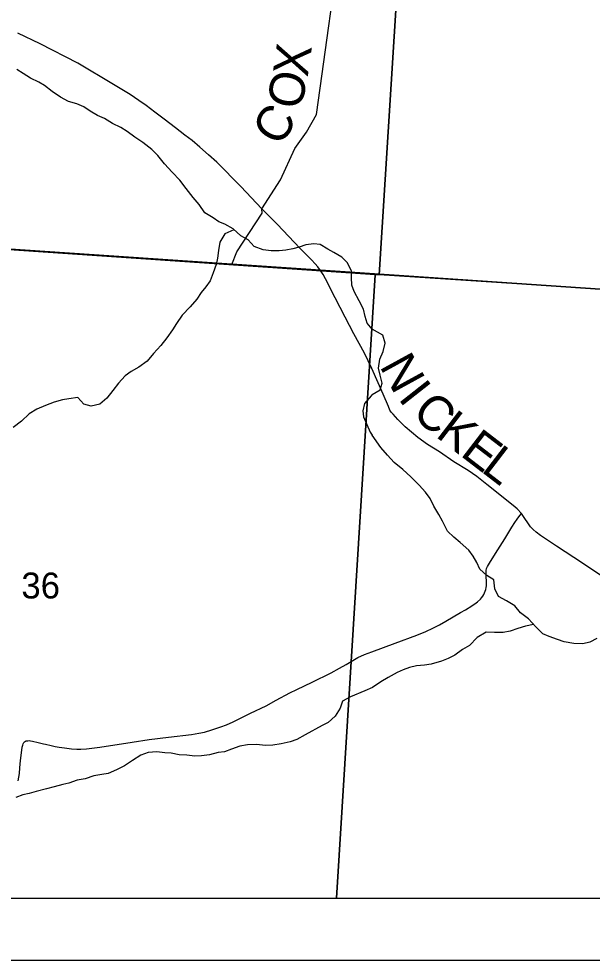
# Model space of a CAD drawing. Extents: x 39.8 to 73.8, y 13 to 35.
# Drawn here: x 43.656 to 44.581, y 26.965 to 28.484 of the extents above; entities that cross this region are included whole.
import ezdxf

# ---------------------------------------------------------------- set-up
doc = ezdxf.new("R2010")
doc.units = 0
for name, color, linetype in [('GM_X_Corporation', 7, 'Continuous'), ('GM_X_County_Road', 7, 'Continuous'), ('GM_X_County_Road_Text', 7, 'Continuous'), ('GM_X_Minor_River', 7, 'Continuous'), ('GM_X_Section_Text', 7, 'Continuous'), ('GM_X_Township_Road', 7, 'Continuous'), ('GM_X_Township_Road_Text', 7, 'Continuous'), ('SH_Data', 7, 'Continuous')]:
    doc.layers.add(name, color=color, linetype=linetype)

msp = doc.modelspace()

# ---------------------------------------------------------------- linework, layer by layer
at = {"layer": 'GM_X_Corporation'}
msp.add_lwpolyline([(43.3304, 29.7365), (43.2726, 28.9503), (43.2721, 28.9438), (43.2131, 28.1416), (43.9992, 28.0883), (44.127, 28.0796), (44.1422, 28.0786), (45.3064, 27.9996), (46.1767, 27.9406), (46.6011, 27.9118), (46.7316, 27.9029), (46.7775, 27.8998), (46.7905, 27.899), (47.095, 27.8783), (47.5149, 27.8498)], dxfattribs=at)
for points in [[(43.2893, 29.1598), (44.3, 29.0715), (44.237, 28.0712), (44.2308, 28.0712), (43.2226, 28.1399)], [(44.3, 29.0715), (45.2916, 29.0179), (45.2324, 28.0059), (44.237, 28.0712)], [(43.1433, 27.065), (48.663, 27.065), (48.663, 27.7809), (47.5414, 27.8484), (47.5149, 27.8498), (47.095, 27.8783), (46.7905, 27.899), (46.7775, 27.8998), (46.7316, 27.9029), (46.6011, 27.9118), (46.1767, 27.9406), (45.3064, 27.9996), (44.1422, 28.0786), (44.127, 28.0796), (43.9992, 28.0883), (43.2131, 28.1416)], [(43.6037, 27.065), (44.1682, 27.065), (44.2308, 28.0712), (43.2226, 28.1399), (43.1518, 27.0988)], [(44.1682, 27.065), (45.172, 27.065), (45.2324, 28.0059), (44.237, 28.0712), (44.2308, 28.0712)]]:
    msp.add_lwpolyline(points, close=True, dxfattribs=at)
at = {"layer": 'GM_X_County_Road'}
for points in [[(44.048, 28.1774), (44.0138, 28.2136), (43.9753, 28.2528), (43.9619, 28.2648), (43.9479, 28.277), (43.9353, 28.2876), (43.9238, 28.2966), (43.9085, 28.3081), (43.8902, 28.3223), (43.875, 28.3338), (43.8612, 28.3442), (43.8491, 28.3525), (43.8355, 28.3619), (43.822, 28.3701), (43.8084, 28.3782), (43.751, 28.4128), (43.6901, 28.4436), (43.6544, 28.461)], [(44.1424, 28.0781), (44.138, 28.0838), (44.1341, 28.0886), (44.1278, 28.0951), (44.1189, 28.1043), (44.109, 28.1142), (44.0729, 28.1521), (44.048, 28.1774)], [(44.4667, 27.6856), (44.4599, 27.6935), (44.4534, 27.6987), (44.411, 27.7325), (44.3944, 27.7454), (44.3807, 27.7552), (44.3578, 27.7693), (44.3343, 27.7852), (44.3153, 27.797), (44.2994, 27.8085), (44.289, 27.817), (44.2792, 27.8257), (44.2674, 27.8375), (44.2595, 27.8462), (44.2567, 27.8495), (44.2544, 27.8528), (44.2522, 27.8587), (44.2438, 27.8786), (44.2253, 27.9201), (44.2135, 27.9444), (44.1962, 27.9759), (44.182, 28.0026), (44.1659, 28.0337), (44.1505, 28.0647), (44.1467, 28.0713), (44.1424, 28.0781)], [(43.6549, 27.2544), (43.6567, 27.2663), (43.6575, 27.2752), (43.6585, 27.2873), (43.66, 27.2995), (43.6614, 27.3087), (43.662, 27.3118), (43.6628, 27.3141), (43.664, 27.3161), (43.6651, 27.3173), (43.6663, 27.3182), (43.6675, 27.3187), (43.6691, 27.3191), (43.6703, 27.3192), (43.6722, 27.3194), (43.6746, 27.3192), (43.6777, 27.3186), (43.6868, 27.3164), (43.6958, 27.3143), (43.699, 27.3134), (43.708, 27.3113), (43.7144, 27.3099), (43.7209, 27.3088), (43.7296, 27.3077), (43.741, 27.3062), (43.7496, 27.3054), (43.7557, 27.3054), (43.7649, 27.306), (43.7864, 27.309), (43.8386, 27.317), (43.8662, 27.3212), (43.8971, 27.3251), (43.9341, 27.3291), (43.9463, 27.3311), (43.9553, 27.3331), (43.9672, 27.3365), (43.9819, 27.3414), (43.9906, 27.3447), (44.0018, 27.3497), (44.0296, 27.3635), (44.0547, 27.3756), (44.071, 27.3844), (44.0929, 27.3964), (44.104, 27.402), (44.1289, 27.4137), (44.1594, 27.4289), (44.1731, 27.4362), (44.1838, 27.4424), (44.1971, 27.4504), (44.2026, 27.4533), (44.2137, 27.4582), (44.2251, 27.4627), (44.263, 27.4767), (44.2979, 27.4897), (44.3122, 27.4956), (44.3235, 27.5008), (44.3344, 27.5063), (44.3446, 27.5121), (44.3682, 27.526), (44.3763, 27.5306), (44.3867, 27.537), (44.3936, 27.5416), (44.396, 27.5433), (44.4004, 27.5475), (44.4024, 27.5498), (44.4041, 27.5523), (44.4057, 27.5549), (44.4071, 27.5576), (44.4082, 27.5604), (44.4091, 27.5633), (44.4098, 27.5662), (44.4102, 27.5692), (44.4105, 27.5753), (44.4099, 27.5846), (44.4095, 27.5909), (44.4098, 27.5941), (44.4105, 27.5972), (44.4117, 27.6002), (44.415, 27.6056), (44.425, 27.6213), (44.4398, 27.645), (44.4509, 27.6637), (44.4558, 27.6715), (44.4595, 27.6767), (44.4639, 27.6826), (44.4667, 27.6856)], [(44.606, 27.5784), (44.5649, 27.6058), (44.5234, 27.633), (44.4975, 27.6502), (44.4902, 27.6557), (44.4856, 27.6598), (44.4815, 27.6643), (44.4778, 27.6692), (44.4709, 27.6795), (44.4667, 27.6856)]]:
    msp.add_lwpolyline(points, dxfattribs=at)
at = {"layer": 'GM_X_Minor_River'}
for p, q in [((43.9881, 28.1372), (43.9802, 28.1235)), ((44.0028, 28.1439), (43.9881, 28.1372)), ((43.9802, 28.1235), (43.978, 28.1102)), ((43.978, 28.1102), (43.9765, 28.0981)), ((43.9765, 28.0981), (43.9743, 28.0878)), ((43.9743, 28.0878), (43.9694, 28.0742)), ((43.9642, 28.0616), (43.9574, 28.0518)), ((43.9694, 28.0742), (43.9642, 28.0616)), ((43.9574, 28.0518), (43.9498, 28.0423)), ((43.9427, 28.032), (43.9321, 28.0194)), ((43.9498, 28.0423), (43.9427, 28.032)), ((43.9321, 28.0194), (43.9193, 28.0057)), ((43.9193, 28.0057), (43.9099, 27.9924)), ((43.9099, 27.9924), (43.9035, 27.9825)), ((43.8948, 27.9692), (43.8851, 27.9571)), ((43.9035, 27.9825), (43.8948, 27.9692)), ((44.2429, 27.9734), (44.2257, 27.9832)), ((44.2468, 27.9609), (44.2429, 27.9734)), ((43.8851, 27.9571), (43.873, 27.9438)), ((44.2435, 27.9472), (44.2468, 27.9609)), ((43.873, 27.9438), (43.8628, 27.9316)), ((44.2383, 27.9347), (44.2435, 27.9472)), ((43.8628, 27.9316), (43.8496, 27.922)), ((44.2362, 27.9206), (44.2383, 27.9347)), ((43.8273, 27.9079), (43.8168, 27.8961)), ((43.8371, 27.9148), (43.8273, 27.9079)), ((43.8496, 27.922), (43.8371, 27.9148)), ((44.2385, 27.9089), (44.2362, 27.9206)), ((44.2421, 27.8964), (44.2385, 27.9089)), ((43.8168, 27.8961), (43.8073, 27.8843)), ((44.2387, 27.8854), (44.2421, 27.8964)), ((43.8073, 27.8843), (43.7979, 27.8718)), ((44.2259, 27.878), (44.2241, 27.8756)), ((44.2259, 27.878), (44.2387, 27.8854)), ((43.7128, 27.8653), (43.6988, 27.86)), ((43.726, 27.8692), (43.7128, 27.8653)), ((43.7366, 27.8708), (43.726, 27.8692)), ((43.751, 27.8731), (43.7366, 27.8708)), ((43.7605, 27.8621), (43.751, 27.8731)), ((43.7726, 27.8588), (43.7605, 27.8621)), ((43.7862, 27.8623), (43.7726, 27.8588)), ((43.7979, 27.8718), (43.7862, 27.8623)), ((44.2135, 27.8634), (44.2105, 27.8517)), ((44.2241, 27.8756), (44.2135, 27.8634)), ((43.6848, 27.8542), (43.6727, 27.8466)), ((43.6988, 27.86), (43.6848, 27.8542)), ((44.2105, 27.8517), (44.2117, 27.8418)), ((43.6599, 27.8348), (43.6467, 27.8245)), ((43.6727, 27.8466), (43.6599, 27.8348)), ((44.2117, 27.8418), (44.217, 27.8293)), ((44.217, 27.8293), (44.2228, 27.8172)), ((44.2228, 27.8172), (44.226, 27.8123)), ((44.2396, 27.7926), (44.226, 27.8123)), ((44.2503, 27.7802), (44.2396, 27.7926)), ((44.2613, 27.7681), (44.2503, 27.7802)), ((44.2754, 27.7569), (44.2613, 27.7681)), ((44.288, 27.7449), (44.2754, 27.7569)), ((44.3014, 27.7318), (44.288, 27.7449)), ((44.3117, 27.7201), (44.3014, 27.7318)), ((44.3193, 27.7103), (44.3117, 27.7201)), ((44.3255, 27.6979), (44.3193, 27.7103)), ((44.3332, 27.6843), (44.3255, 27.6979)), ((44.339, 27.6734), (44.3332, 27.6843)), ((44.3474, 27.6575), (44.339, 27.6734)), ((44.3577, 27.6474), (44.3474, 27.6575)), ((44.368, 27.6388), (44.3577, 27.6474)), ((44.3817, 27.6268), (44.368, 27.6388)), ((44.389, 27.617), (44.3817, 27.6268)), ((44.3948, 27.6068), (44.389, 27.617)), ((44.3994, 27.5962), (44.3948, 27.6068)), ((44.4109, 27.5857), (44.3994, 27.5962)), ((44.4219, 27.5786), (44.4109, 27.5857)), ((44.4235, 27.5642), (44.4219, 27.5786)), ((44.4297, 27.5518), (44.4235, 27.5642)), ((44.4426, 27.5447), (44.4297, 27.5518)), ((44.4559, 27.5369), (44.4426, 27.5447)), ((44.4651, 27.5256), (44.4559, 27.5369)), ((44.4781, 27.5158), (44.4651, 27.5256)), ((44.4899, 27.5027), (44.4781, 27.5158)), ((44.4608, 27.5005), (44.4483, 27.4962)), ((44.4732, 27.504), (44.4608, 27.5005)), ((44.4863, 27.5067), (44.4732, 27.504)), ((44.5014, 27.4914), (44.4899, 27.5027)), ((44.3951, 27.4855), (44.3827, 27.4729)), ((44.4098, 27.4944), (44.3951, 27.4855)), ((44.423, 27.4937), (44.4098, 27.4944)), ((44.437, 27.4939), (44.423, 27.4937)), ((44.4483, 27.4962), (44.437, 27.4939)), ((44.5112, 27.4873), (44.5014, 27.4914)), ((44.5249, 27.4825), (44.5112, 27.4873)), ((44.5355, 27.4788), (44.5249, 27.4825)), ((44.5884, 27.4843), (44.5768, 27.4781)), ((44.3827, 27.4729), (44.3718, 27.4664)), ((44.5511, 27.476), (44.5355, 27.4788)), ((44.5654, 27.4753), (44.5511, 27.476)), ((44.5768, 27.4781), (44.5654, 27.4753)), ((44.3594, 27.4572), (44.3485, 27.4518)), ((44.3718, 27.4664), (44.3594, 27.4572)), ((44.2862, 27.4375), (44.276, 27.4333)), ((44.2975, 27.4399), (44.2862, 27.4375)), ((44.31, 27.4412), (44.2975, 27.4399)), ((44.3209, 27.4428), (44.31, 27.4412)), ((44.3375, 27.4475), (44.3209, 27.4428)), ((44.3485, 27.4518), (44.3375, 27.4475)), ((44.2662, 27.429), (44.2515, 27.4213)), ((44.276, 27.4333), (44.2662, 27.429)), ((44.2398, 27.414), (44.2265, 27.4049)), ((44.2515, 27.4213), (44.2398, 27.414))]:
    msp.add_line(p, q, dxfattribs=at)
for points in [[(44.2257, 27.9832), (44.2176, 27.9931), (44.2145, 28.0036), (44.2118, 28.0158), (44.205, 28.029), (44.1966, 28.0441), (44.1932, 28.0543), (44.1924, 28.0668), (44.1923, 28.0767), (44.1862, 28.0903), (44.1767, 28.0994), (44.1638, 28.1073), (44.1543, 28.1125), (44.1418, 28.1197), (44.1316, 28.1211), (44.1187, 28.1192), (44.1082, 28.1154), (44.098, 28.113), (44.0866, 28.1107), (44.0756, 28.1099), (44.0631, 28.1095), (44.0499, 28.1113), (44.0355, 28.1165), (44.0256, 28.1275), (44.0139, 28.1339), (44.0013, 28.1452), (43.9881, 28.1527), (43.9786, 28.1565), (43.9691, 28.1629), (43.9558, 28.1711), (43.9467, 28.1847), (43.9368, 28.1957), (43.9258, 28.2104), (43.9155, 28.2236), (43.9034, 28.2365), (43.8908, 28.2501), (43.8798, 28.2637), (43.8703, 28.2731), (43.8559, 28.2848), (43.843, 28.2931), (43.8308, 28.3021), (43.8202, 28.3089), (43.807, 28.3153), (43.7941, 28.3232), (43.7827, 28.328), (43.7706, 28.3352), (43.7607, 28.342), (43.7493, 28.3468), (43.7361, 28.3506), (43.7228, 28.3577), (43.7095, 28.3667), (43.6974, 28.3765), (43.6879, 28.3822), (43.6746, 28.3886), (43.6625, 28.3961), (43.6526, 28.4025)], [(44.2265, 27.4049), (44.214, 27.3999), (44.1906, 27.3899), (44.1781, 27.3831), (44.174, 27.3717), (44.1661, 27.3588), (44.1548, 27.3485), (44.145, 27.3439), (44.1178, 27.3286), (44.1042, 27.3213), (44.0936, 27.3171), (44.0788, 27.314), (44.0656, 27.3117), (44.0531, 27.3116), (44.0395, 27.3131), (44.0247, 27.3123), (44.0122, 27.3103), (43.999, 27.3053), (43.9877, 27.3011), (43.9774, 27.2999), (43.9635, 27.2961), (43.9502, 27.2949), (43.9396, 27.2944), (43.9267, 27.2959), (43.9146, 27.2966), (43.9017, 27.2992), (43.8915, 27.2995), (43.8783, 27.301), (43.8643, 27.3002), (43.8526, 27.2956), (43.839, 27.2872), (43.8265, 27.2788), (43.8133, 27.2719), (43.8001, 27.2665), (43.7895, 27.2646), (43.7766, 27.2626), (43.7626, 27.2577), (43.7501, 27.2553), (43.7365, 27.2507), (43.7267, 27.2484), (43.7127, 27.2449), (43.7006, 27.2415), (43.684, 27.2372), (43.6722, 27.2341), (43.6624, 27.2318), (43.6507, 27.2276)]]:
    msp.add_lwpolyline(points, dxfattribs=at)
at = {"layer": 'GM_X_Township_Road'}
for points in [[(44.048, 28.1774), (44.0781, 28.2243), (44.1008, 28.2748), (44.1198, 28.3014), (44.1361, 28.3299), (44.1418, 28.3724), (44.1724, 28.5933), (44.1568, 28.6328), (44.1792, 28.7235), (44.197, 28.7687), (44.23, 28.7972), (44.2647, 28.8388), (44.2842, 28.8692), (44.3021, 28.8926), (44.4348, 28.9977), (44.4771, 29.0245), (44.4889, 29.0403), (44.521, 29.0631), (44.5248, 29.1497)], [(43.9994, 28.0878), (44.0073, 28.1079), (44.0481, 28.1704), (44.048, 28.1774)]]:
    msp.add_lwpolyline(points, dxfattribs=at)
at = {"layer": 'SH_Data'}
for p, q in [((41.863, 27.065), (48.663, 27.065)), ((41.763, 26.965), (48.763, 26.965))]:
    msp.add_line(p, q, dxfattribs=at)

# ---------------------------------------------------------------- texts
at = {"layer": 'GM_X_County_Road_Text'}
for s, rotation, p in [('N', 298.7137, (44.2369, 27.9239)), ('I', 308.2168, (44.2666, 27.8715)), ('C', 317.72, (44.288, 27.8456)), ('K', 322.4716, (44.3265, 27.8109)), ('E', 322.4716, (44.3662, 27.7804)), ('L', 322.4716, (44.3999, 27.7546))]:
    msp.add_text(s, height=0.0568, rotation=rotation, dxfattribs=at).set_placement(p)
at = {"layer": 'GM_X_Section_Text'}
msp.add_text('36', height=0.04186, rotation=0, dxfattribs=at).set_placement((43.6599, 27.5487))
at = {"layer": 'GM_X_Township_Road_Text'}
for s, rotation, p in [('X', 81.9812, (44.1217, 28.3891)), ('O', 77.8123, (44.1104, 28.3357)), ('C', 57.5159, (44.077, 28.2762))]:
    msp.add_text(s, height=0.0568, rotation=rotation, dxfattribs=at).set_placement(p)

doc.saveas('drawing.dxf')
